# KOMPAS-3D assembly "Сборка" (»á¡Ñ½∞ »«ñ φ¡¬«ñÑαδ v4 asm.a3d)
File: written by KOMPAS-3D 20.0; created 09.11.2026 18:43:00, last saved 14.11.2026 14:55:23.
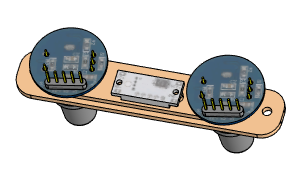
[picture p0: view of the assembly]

Document properties: Полное имя файла: D:\RicWork\Project-EPS32\box_compas\сборки компонентов\панель под энкодеры v4 asm.a3d

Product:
- Part/product: Сборка
    Масса: 0.0719376
  - Component [assembly]: Сборка  | qty 2  | Масса: 0.0191475; source file: ..\переключатели и кнопки\TZT_EC11 asm.a3d
  - Component [detail]: Деталь  | Масса: 0.00714876; source file: ..\переключатели и кнопки\indicator typa B without button.m3d
  - Component [detail]: Деталь  | Масса: 0.0264939; source file: ..\корпус\панель под энкодеры v4.m3d

Referenced files in D:\RicWork\Project-EPS32\box_compas\переключатели и кнопки\: indicator typa B without button.m3d, TZT_EC11 asm.a3d
Referenced files in D:\RicWork\Project-EPS32\box_compas\корпус\: панель под энкодеры v4.m3d
Referenced files in D:\myProjects\Progect_esp32\box_compas\переключатели и кнопки\: TZT_EC11 asm.a3d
